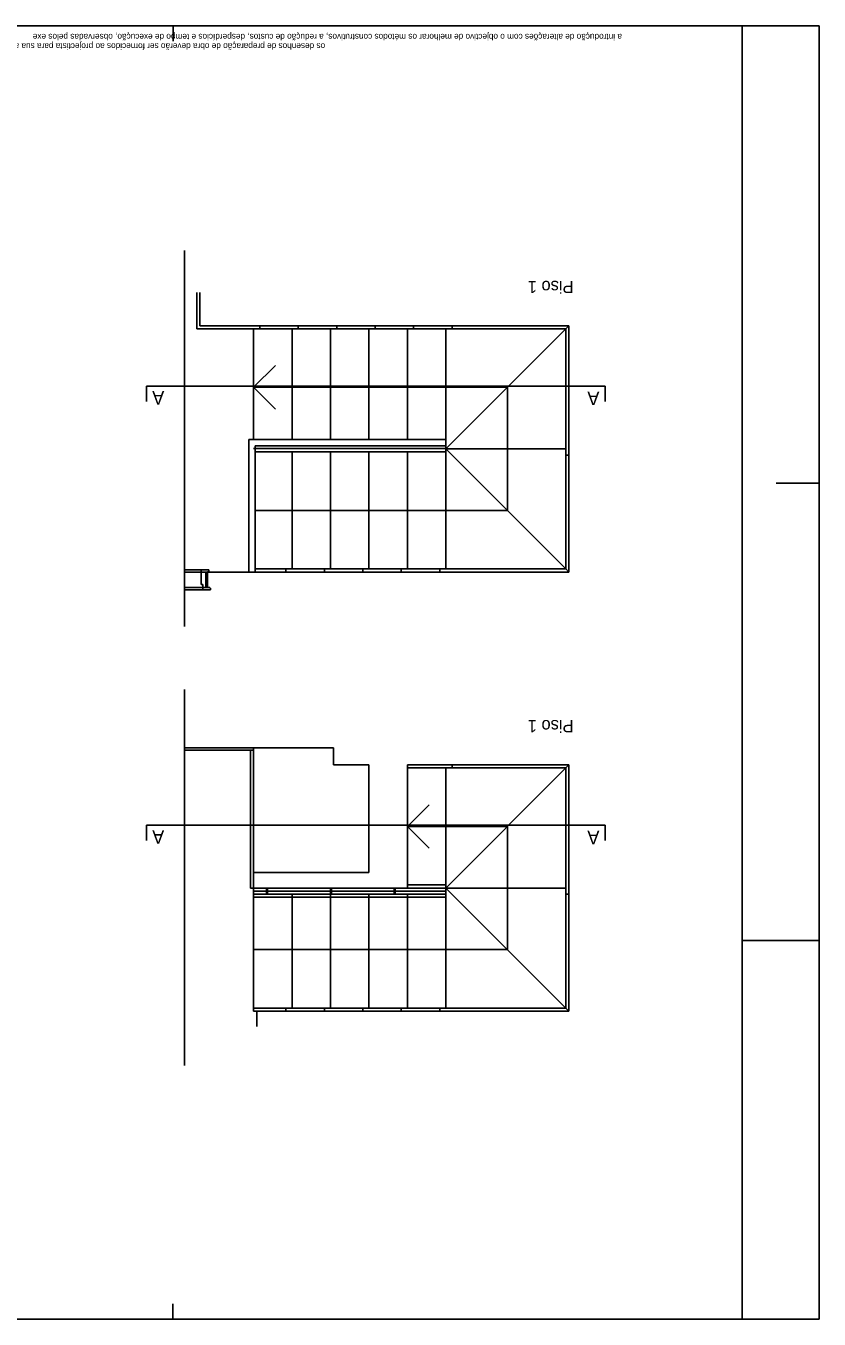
# Model space of a CAD drawing. Extents: x 1290.7 to 1314.8, y -291.6 to -265.9.
# Drawn here: x 1309.66 to 1314.82, y -274.35 to -265.95 of the extents above; entities that cross this region are included whole.
import ezdxf

# ---------------------------------------------------------------- set-up
doc = ezdxf.new("R2010")
doc.units = 0
for name, color, linetype in [('Level 1', 7, 'Continuous'), ('Level 10', 7, 'Continuous'), ('Level 13', 7, 'Continuous'), ('Level 2', 7, 'Continuous'), ('Level 4', 7, 'Continuous'), ('Level 59', 7, 'Continuous'), ('Level 60', 7, 'Continuous'), ('Level 62', 7, 'Continuous')]:
    doc.layers.add(name, color=color, linetype=linetype)

msp = doc.modelspace()

# ---------------------------------------------------------------- linework, layer by layer
at = {"layer": 'Level 1'}
for p, q in [((1310.78899, -267.68143), (1310.78899, -267.89643)), ((1313.18899, -267.89643), (1310.78899, -267.89643)), ((1313.18899, -267.89643), (1313.18899, -269.49643)), ((1313.18899, -269.49643), (1310.83899, -269.49643)), ((1310.83899, -269.59643), (1310.83899, -269.49643)), ((1310.83899, -269.50643), (1310.83899, -269.49643)), ((1310.83899, -269.59643), (1310.83899, -269.58643)), ((1310.68899, -270.63885), (1311.65935, -270.63885)), ((1311.65935, -270.63885), (1311.65935, -270.74885)), ((1311.88899, -270.74885), (1311.65935, -270.74885)), ((1311.88899, -270.74885), (1311.88899, -271.44885)), ((1312.13899, -270.74885), (1312.13899, -271.54885)), ((1312.13899, -270.74885), (1313.18899, -270.74885)), ((1313.18899, -270.74885), (1313.18899, -272.34885)), ((1313.18899, -270.74885), (1313.18899, -272.34885)), ((1311.88899, -271.44885), (1311.13899, -271.44885)), ((1311.13899, -271.54885), (1311.13899, -271.44885)), ((1312.13899, -271.54885), (1311.13899, -271.54885)), ((1313.18899, -272.34885), (1311.15899, -272.34885)), ((1311.15899, -272.34885), (1311.15899, -272.44885)), ((1313.18899, -272.34885), (1311.48899, -272.34885))]:
    msp.add_line(p, q, dxfattribs=at)
at = {"layer": 'Level 10'}
for p, q in [((1310.79899, -269.49643), (1310.68899, -269.49643)), ((1310.80899, -269.59643), (1310.68899, -269.59643))]:
    msp.add_line(p, q, dxfattribs=at)
at = {"layer": 'Level 13'}
for p, q in [((1310.76899, -267.68143), (1310.76899, -267.91643)), ((1313.16899, -267.91643), (1310.76899, -267.91643)), ((1311.17899, -267.89643), (1311.17899, -267.91643)), ((1311.42899, -267.89643), (1311.42899, -267.91643)), ((1311.67899, -267.89643), (1311.67899, -267.91643)), ((1311.92899, -267.89643), (1311.92899, -267.91643)), ((1312.17899, -267.89643), (1312.17899, -267.91643)), ((1312.42899, -267.89643), (1312.42899, -267.91643)), ((1313.16899, -267.91643), (1313.18899, -267.89643)), ((1313.16899, -267.91643), (1313.16899, -269.47643)), ((1313.18899, -268.73643), (1313.16899, -268.73643)), ((1310.84899, -269.48143), (1310.79899, -269.48143)), ((1310.79899, -269.48143), (1310.79899, -269.49643)), ((1310.82899, -269.49643), (1310.79899, -269.49643)), ((1310.79899, -269.49643), (1310.79899, -269.57643)), ((1310.79899, -269.49643), (1310.84399, -269.49643)), ((1310.82899, -269.59643), (1310.82899, -269.49643)), ((1310.84399, -269.49643), (1310.84399, -269.49143)), ((1310.84399, -269.49143), (1310.84899, -269.49143)), ((1310.84899, -269.49143), (1310.84899, -269.48143)), ((1313.16899, -269.47643), (1311.14899, -269.47643)), ((1311.34899, -269.47643), (1311.34899, -269.49643)), ((1311.59899, -269.47643), (1311.59899, -269.49643)), ((1311.84899, -269.47643), (1311.84899, -269.49643)), ((1312.09899, -269.47643), (1312.09899, -269.49643)), ((1312.34899, -269.47643), (1312.34899, -269.49643)), ((1313.16899, -269.47643), (1313.18899, -269.49643)), ((1310.79899, -269.57643), (1310.80899, -269.57643)), ((1310.80899, -269.57643), (1310.80899, -269.59643)), ((1310.80899, -269.59643), (1310.82899, -269.59643)), ((1310.80899, -269.61143), (1310.80899, -269.59643)), ((1310.80899, -269.59643), (1310.85399, -269.59643)), ((1310.85899, -269.61143), (1310.80899, -269.61143)), ((1310.85399, -269.59643), (1310.85399, -269.60143)), ((1310.85399, -269.60143), (1310.85899, -269.60143)), ((1310.85899, -269.60143), (1310.85899, -269.61143)), ((1311.13899, -271.54885), (1311.13899, -270.63885)), ((1310.68899, -270.65385), (1311.13899, -270.65385)), ((1311.11899, -271.54885), (1311.11899, -270.65385)), ((1313.16899, -270.76885), (1312.13899, -270.76885)), ((1312.42899, -270.74885), (1312.42899, -270.76885)), ((1313.16899, -270.76885), (1313.18899, -270.74885)), ((1313.16899, -270.76885), (1313.16899, -272.32885)), ((1311.13899, -271.54885), (1311.11899, -271.54885)), ((1313.16899, -271.58885), (1313.18899, -271.58885)), ((1313.16899, -272.32885), (1311.13899, -272.32885)), ((1311.15899, -272.34885), (1311.13899, -272.34885)), ((1311.34899, -272.32885), (1311.34899, -272.34885)), ((1311.59899, -272.32885), (1311.59899, -272.34885)), ((1311.84899, -272.32885), (1311.84899, -272.34885)), ((1312.09899, -272.32885), (1312.09899, -272.34885)), ((1312.34899, -272.32885), (1312.34899, -272.34885)), ((1313.16899, -272.32885), (1313.18899, -272.34885))]:
    msp.add_line(p, q, dxfattribs=at)
at = {"layer": 'Level 2'}
for p, q in [((1311.13899, -267.91643), (1311.13899, -268.63643)), ((1311.38899, -267.91643), (1311.38899, -268.63643)), ((1311.63899, -267.91643), (1311.63899, -268.63643)), ((1311.88899, -267.91643), (1311.88899, -268.63643)), ((1312.13899, -267.91643), (1312.13899, -268.63643)), ((1312.38899, -267.91643), (1312.38899, -268.66643)), ((1312.38899, -268.69643), (1313.16899, -267.91643)), ((1311.28041, -268.15501), (1311.13899, -268.29643)), ((1312.78899, -268.29643), (1311.13899, -268.29643)), ((1311.28041, -268.43785), (1311.13899, -268.29643)), ((1312.78899, -268.29643), (1312.78899, -269.09643)), ((1311.10899, -268.63643), (1311.10899, -269.49643)), ((1312.38899, -268.63643), (1311.10899, -268.63643)), ((1312.38899, -268.67643), (1311.14899, -268.67643)), ((1311.14899, -268.67643), (1311.14899, -269.49643)), ((1312.38899, -268.72643), (1312.38899, -268.66643)), ((1313.16899, -268.69643), (1312.38899, -268.69643)), ((1312.38899, -268.69643), (1313.16899, -269.47643)), ((1312.38899, -268.71643), (1311.14899, -268.71643)), ((1311.38899, -268.71643), (1311.38899, -269.47643)), ((1311.63899, -268.71643), (1311.63899, -269.47643)), ((1311.88899, -268.71643), (1311.88899, -269.47643)), ((1312.13899, -268.71643), (1312.13899, -269.47643)), ((1312.38899, -268.72643), (1312.38899, -269.47643)), ((1311.14899, -269.09643), (1312.78899, -269.09643)), ((1312.38899, -270.76885), (1312.38899, -271.51885)), ((1312.38899, -271.54885), (1313.16899, -270.76885)), ((1312.28041, -271.00743), (1312.13899, -271.14885)), ((1312.28041, -271.29027), (1312.13899, -271.14885)), ((1312.78899, -271.14885), (1312.13899, -271.14885)), ((1312.78899, -271.14885), (1312.78899, -271.94885)), ((1311.13899, -272.32885), (1311.13899, -271.54885)), ((1312.38899, -271.56885), (1311.13899, -271.56885)), ((1311.13899, -271.56885), (1311.13899, -272.34885)), ((1311.22343, -271.54885), (1311.22343, -271.56885)), ((1311.23011, -271.54885), (1311.23011, -271.56885)), ((1311.6385, -271.54885), (1311.6385, -271.56885)), ((1311.64518, -271.54885), (1311.64518, -271.56885)), ((1312.38899, -271.52885), (1312.13899, -271.52885)), ((1312.38899, -271.57885), (1312.38899, -271.51885)), ((1313.16899, -271.54885), (1312.38899, -271.54885)), ((1312.38899, -271.54885), (1313.16899, -272.32885)), ((1312.38899, -271.60885), (1311.13899, -271.60885)), ((1311.38899, -271.60885), (1311.38899, -272.32885)), ((1311.63899, -271.60885), (1311.63899, -272.32885)), ((1311.88899, -271.60885), (1311.88899, -272.32885)), ((1312.13899, -271.60885), (1312.13899, -272.32885)), ((1312.38899, -271.57885), (1312.38899, -272.32885)), ((1311.13899, -271.94885), (1312.78899, -271.94885))]:
    msp.add_line(p, q, dxfattribs=at)
at = {"layer": 'Level 4'}
for p, q in [((1312.38899, -268.69443), (1311.13899, -268.69443)), ((1310.68899, -269.48143), (1310.79899, -269.48143)), ((1310.80899, -269.61143), (1310.68899, -269.61143)), ((1311.22343, -271.56752), (1311.22343, -271.58885)), ((1311.23011, -271.56752), (1311.23011, -271.58885)), ((1311.6385, -271.56752), (1311.6385, -271.58885)), ((1311.64518, -271.56885), (1311.64518, -271.58885)), ((1311.88899, -271.54885), (1312.38899, -271.54885)), ((1312.05313, -271.54885), (1312.05313, -271.58885)), ((1312.05981, -271.54885), (1312.05981, -271.58885)), ((1312.38899, -271.58885), (1311.13899, -271.58885)), ((1311.38899, -271.60885), (1311.38899, -271.58885)), ((1311.63899, -271.60885), (1311.63899, -271.58885)), ((1311.88899, -271.60885), (1311.88899, -271.58885)), ((1312.13899, -271.60885), (1312.13899, -271.58885))]:
    msp.add_line(p, q, dxfattribs=at)
at = {"layer": 'Level 59'}
for p, q in [((1310.68899, -267.40778), (1310.68899, -269.84976)), ((1313.42488, -268.28866), (1310.44183, -268.28866)), ((1310.44183, -268.28866), (1310.44183, -268.38846)), ((1313.42488, -268.28866), (1313.42488, -268.38846)), ((1310.68899, -270.2602), (1310.68899, -272.70218)), ((1313.42488, -271.14108), (1310.44183, -271.14108)), ((1310.44183, -271.14108), (1310.44183, -271.24088)), ((1313.42488, -271.14108), (1313.42488, -271.24088))]:
    msp.add_line(p, q, dxfattribs=at)
at = {"layer": 'Level 62'}
for p, q in [((1310.61549, -266.04881), (1310.61549, -265.94881)), ((1314.31509, -274.34881), (1314.31509, -265.94881)), ((1314.81509, -268.91881), (1314.53509, -268.91881)), ((1313.10899, -269.49643), (1312.83834, -269.49643)), ((1313.10899, -270.74885), (1312.83834, -270.74885)), ((1314.31509, -271.88881), (1314.81509, -271.88881)), ((1313.10899, -272.34885), (1312.83834, -272.34885)), ((1310.61469, -274.24881), (1310.61469, -274.34881)), ((1314.31509, -274.34881), (1314.81509, -274.34881))]:
    msp.add_line(p, q, dxfattribs=at)
msp.add_lwpolyline([(1314.81509, -265.94881), (1314.81509, -274.34881), (1303.21549, -274.34881), (1303.21549, -265.94881)], close=True, dxfattribs=at)

# ---------------------------------------------------------------- texts
at = {"layer": 'Level 59'}
for rotation, p in [(180.000181, (1310.5584, -268.32048)), (179.999819, (1313.38686, -268.32432)), (180.000181, (1310.5584, -271.1729)), (179.999819, (1313.38686, -271.17674))]:
    msp.add_text('A', height=0.088, rotation=rotation, dxfattribs=at).set_placement(p)
at = {"layer": 'Level 60'}
for p in [(1313.21848, -267.60497), (1313.21848, -270.45739)]:
    msp.add_text('Piso 1', height=0.08, rotation=180.000011, dxfattribs=at).set_placement(p)
at = {"layer": 'Level 62'}
for s, p in [('a introdução de alterações com o objectivo de melhorar os métodos construtivos, a redução de custos, desperdícios e tempo de execução, observadas pelos exe', (1313.53328, -266.00081)), ('os desenhos de preparação de obra deverão ser fornecidos ao projectista para sua aprovação -', (1311.60428, -266.06181))]:
    msp.add_text(s, height=0.0399996, rotation=180, dxfattribs=at).set_placement(p)

doc.saveas('drawing.dxf')
